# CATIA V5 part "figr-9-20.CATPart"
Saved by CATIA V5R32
Part number: Part3
Bounding box of the stored display mesh (mm): x -112 to 0, y -101.683 to 100, z -80.304 to 44.415
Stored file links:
  D:\PROJECTS\Project 2022\CATIA V5 6R 2022\Resources\Part Files\c09_catia_v5_6r2022_prt\c09_catia_v5_6r2022_prt\figr-9-20.CATPart
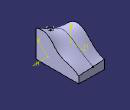
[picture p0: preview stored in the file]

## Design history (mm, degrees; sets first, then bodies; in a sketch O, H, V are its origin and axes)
Set1
  Plane1: type Offset, RefPlane yz-plane, Offset -112
  Plane2: type Offset, RefPlane yz-plane, Offset -63
  Plane3: type Normal, Curve Sketch4, RefPoint vertex of Sketch4
Body1 (main body)
  Sketch1 on yz-plane, origin (0, 0, 0), H (0, 1, 0), V (0, 0, 1)
    spline S1 through (-92.6897, 40.1119) (-30, 30) (10, -10) (60, -30) (97.3103, -50.3041)
    line L1 (97.3103, -50.3041) -> (97.3103, -80.3041)
    line L2 (97.3103, -80.3041) -> (-92.6897, -80.3041)
    line L3 (-92.6897, -80.3041) -> (-92.6897, 40.1119)
    point P3 (-92.6897, 40.1119)
    point P4 (97.3103, -50.3041)
    point P5 (-92.6897, 40.1119)
    point P6 (97.3103, -50.3041)
    vertical: L1 V, L3 V
    horizontal: L2 H
    coincidence: P5 P3, P6 P4
  Sketch2 on Plane1, origin (-112, 0, 0), H (0, 1, 0), V (0, 0, 1)
    spline S1 through (-90, -30) (-70, 10) (-20, 40) (40, 0) (100, -40)
    line L1 (100, -40) -> (100, -80)
    line L2 (100, -80) -> (-90, -80)
    line L3 (-90, -80) -> (-90, -30)
    point P3 (-90, -30)
    point P4 (100, -40)
    point P5 (40, 0)
    point P6 (-90, -30)
    point P7 (100, -40)
    coincidence: P5 H, P6 P3, P7 P4
    vertical: L1 V, L3 V
    horizontal: L2 H
  Loft1: Sections (Sketch1; Sketch2)
  Sketch3 on Plane3, origin (0, -40.1726, -44.9298), H (1, 0, 0), V (0, -0.7455, 0.6665)
    point P1 (-63, 68.4187)
    line L1 (-63, 68.4187) -> (-75.2117, 62.4925)
    line L2 (-75.2117, 62.4925) -> (-79.6266, 71.5898)
    line L3 (-79.6266, 71.5898) -> (-57.1205, 82.5119)
    line L4 (-57.1205, 82.5119) -> (-52.7056, 73.4145)
    point P5 (-52.7056, 73.4145)
    line L5 (-52.7056, 73.4145) -> (-63, 68.4187)
    reference projected point E1 (-63, 68.4187) from vertex of Sketch4
    perpendicularity: L2 L1
    parallelism: L3 L1, L4 L2, L5 L1
    coincidence: P5 L1, P1 E1
  Sketch4 on Plane2, origin (-63, 0, 0), H (0, 1, 0), V (0, 0, 1)
    intersected curve E1 from face of Loft1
